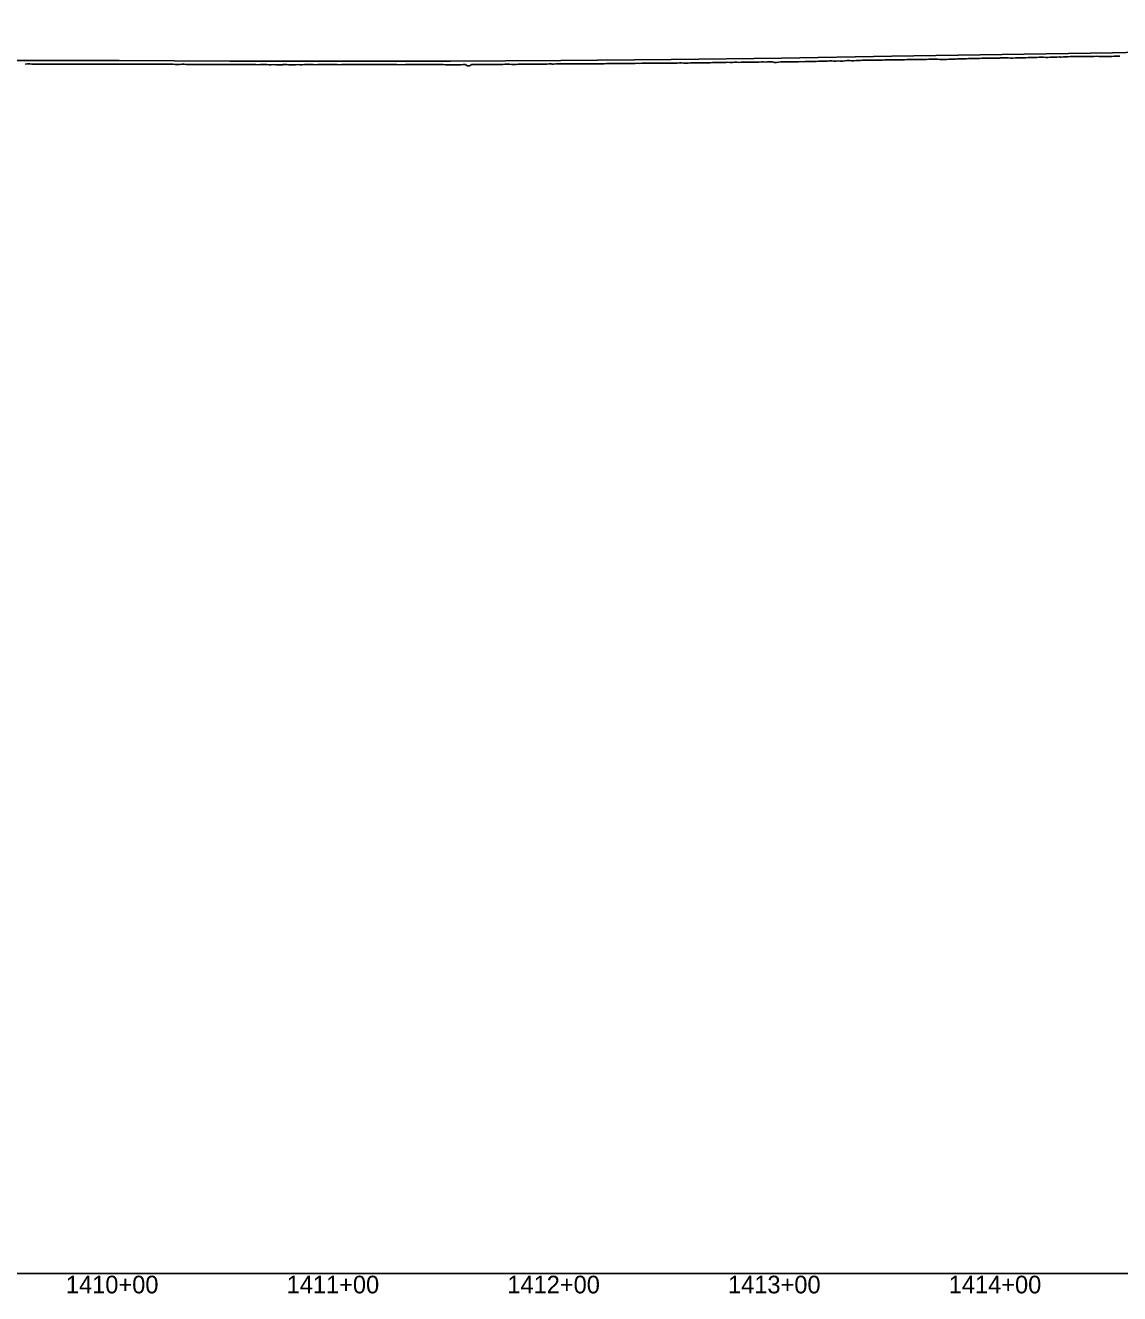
# Model space of a CAD drawing. Extents: x -3793 to 50787, y -1075 to 6138.
# Drawn here: x 28283 to 28779, y 2991 to 3566 of the extents above; entities that cross this region are included whole.
import ezdxf

# ---------------------------------------------------------------- set-up
doc = ezdxf.new("R2010")
doc.units = 0
for name, color, linetype in [('RD_DDB_Profile_EX', 7, 'Continuous'), ('RD_DDB_Profile_PR', 7, 'Continuous'), ('RD_DDB_StaTX', 7, 'Continuous'), ('RD_GPK_Profile_Cell', 7, 'Continuous')]:
    doc.layers.add(name, color=color, linetype=linetype)

msp = doc.modelspace()

# ---------------------------------------------------------------- linework, layer by layer
at = {"layer": 'RD_DDB_Profile_EX'}
for points in [[(28283.238508, 3548.117), (28284.232974, 3548.16193), (28285.312844, 3548.162625), (28286.238026, 3548.117085), (28287.231895, 3548.025065), (28288.236227, 3548.02389), (28289.316176, 3547.9783), (28290.232175, 3548.024735), (28291.31317, 3548.11187), (28291.877983, 3548.084065), (28292.238714, 3548.066225), (28293.310113, 3548.02396), (28294.235423, 3548.070475), (28295.316133, 3548.02279), (28296.232852, 3547.976725), (28297.312241, 3547.97316), (28298.237906, 3548.019695), (28298.885813, 3547.973355), (28299.889108, 3548.021675), (28300.882818, 3548.06394), (28301.885791, 3548.017785), (28302.88791, 3548.01794), (28303.890883, 3548.11034), (28304.883836, 3548.06784), (28305.416907, 3548.041355), (28305.886792, 3548.01776), (28306.889629, 3548.110085), (28307.882641, 3548.109595), (28308.885478, 3548.07094), (28309.888413, 3548.028325), (28310.890498, 3548.07445), (28311.884261, 3548.11638), (28312.186369, 3548.1013), (28312.887073, 3548.06994)], [(28312.887073, 3548.06994), (28313.889221, 3548.02324), (28314.870636, 3548.07271), (28315.87335, 3548.115065), (28316.876172, 3548.064775), (28317.869093, 3548.06418), (28318.95583, 3548.06402), (28319.874612, 3548.063545), (28320.877415, 3548.063025), (28321.870213, 3548.06234), (28322.873017, 3548.0155), (28323.87582, 3548.05764), (28324.869342, 3548.10334), (28325.872141, 3548.10645), (28326.874104, 3548.059455), (28327.876891, 3548.06231), (28328.870489, 3548.107665), (28329.873171, 3548.10348), (28330.875252, 3548.10272), (28331.86884, 3548.051705), (28332.494754, 3548.051245), (28332.871518, 3548.051015), (28333.874287, 3548.10005), (28334.868477, 3548.09359), (28335.87115, 3548.092775), (28336.873919, 3548.095205), (28338.235968, 3548.09582), (28339.264216, 3548.04977), (28340.229246, 3548.04705), (28341.230114, 3548.049405), (28342.231734, 3548.003475), (28343.232598, 3548.00418), (28344.234217, 3548.05125), (28345.235081, 3548.007165), (28346.236625, 3548.004255), (28347.237442, 3548.050985), (28348.238975, 3548.008525), (28349.230427, 3548.00689), (28350.231963, 3548.00723), (28351.232767, 3547.96488), (28352.234242, 3547.96538), (28352.803139, 3547.96679), (28353.234984, 3547.971185), (28354.236376, 3548.021455), (28355.237828, 3548.017845), (28356.238535, 3547.9254), (28357.239164, 3547.92758), (28358.240617, 3547.97014), (28359.24207, 3547.92782), (28359.572601, 3547.927805), (28360.226492, 3547.923935), (28361.226135, 3547.922125), (28362.227373, 3547.922305), (28363.228681, 3547.918505), (28364.229919, 3547.914845), (28365.230385, 3547.912735), (28366.342063, 3547.916785), (28367.232797, 3547.916755), (28368.234035, 3547.87043), (28369.234361, 3547.86824), (28370.235599, 3547.964135), (28371.227569, 3547.91773), (28372.227902, 3547.881235), (28373.229131, 3547.873125), (28374.230228, 3547.868915), (28375.231396, 3547.87241), (28376.23166, 3547.88181), (28377.232756, 3547.881515), (28378.233925, 3547.877125), (28378.843878, 3547.86459), (28379.880986, 3547.86586), (28380.766657, 3547.869235), (28381.846337, 3547.91098), (28382.767684, 3547.912065), (28383.76896, 3547.961445), (28384.769348, 3547.86487), (28385.848868, 3547.86824), (28386.770482, 3547.91542), (28387.771646, 3547.860785), (28388.85097, 3547.81783), (28389.763651, 3547.86459), (28390.764923, 3547.86763), (28391.766085, 3547.866895), (28392.767248, 3547.85457), (28393.767211, 3547.81307), (28394.76837, 3547.769855), (28395.846348, 3547.857275), (28396.769491, 3547.76568), (28397.770652, 3547.764715), (28398.771922, 3547.813605), (28399.848749, 3547.808915), (28400.189371, 3547.82629), (28400.763786, 3547.855465), (28401.76505, 3547.85419), (28402.766208, 3547.80678), (28403.766164, 3547.807195), (28404.767323, 3547.806025), (28405.768483, 3547.808545), (28406.958833, 3547.840485), (28407.768872, 3547.800235), (28408.770143, 3547.79874)], [(28408.770143, 3547.79874), (28409.843205, 3547.8474), (28410.761974, 3547.893865), (28411.763239, 3547.845965), (28412.782954, 3547.89456), (28413.783944, 3547.84318), (28414.783889, 3547.79665), (28415.784855, 3547.84157), (28416.634545, 3547.841215), (28417.634416, 3547.84132), (28418.634359, 3547.8413), (28419.63423, 3547.88796), (28420.634095, 3547.888035), (28421.633028, 3547.889455), (28422.632856, 3547.89283), (28423.632684, 3547.8962), (28424.632585, 3547.84596), (28425.632413, 3547.79237), (28426.632241, 3547.84226), (28427.632054, 3547.93514), (28428.631912, 3547.89162), (28429.631699, 3547.887845), (28430.631485, 3547.937525), (28431.631342, 3547.89394), (28432.639717, 3547.89383), (28433.639507, 3547.89008), (28434.03668, 3547.88995), (28434.639344, 3547.886095), (28435.639698, 3547.885705), (28436.639376, 3547.835295), (28437.639124, 3547.88476), (28438.638802, 3547.88435), (28439.638551, 3547.83382), (28440.806142, 3547.87159), (28441.637878, 3547.83282), (28442.636611, 3547.833735), (28443.636252, 3547.88311), (28444.635894, 3547.839105), (28445.636262, 3547.83834), (28446.635902, 3547.884405), (28447.63554, 3547.883745), (28448.635212, 3547.832765), (28449.634817, 3547.8319), (28450.634489, 3547.83092), (28451.634096, 3547.82688), (28452.632724, 3547.780895), (28453.632397, 3547.829915), (28454.631015, 3547.783885), (28455.630246, 3547.83134), (28456.638218, 3547.88208), (28457.636812, 3547.88271), (28458.635473, 3547.886465), (28459.634067, 3547.883845), (28460.632661, 3547.88119), (28461.114527, 3547.905615), (28461.631305, 3547.931575), (28462.629865, 3547.93857), (28463.637715, 3547.932595), (28464.636342, 3547.882875), (28465.636535, 3547.88492), (28466.635095, 3547.88533), (28467.883989, 3547.923185), (28468.632259, 3547.88586), (28469.630855, 3547.885935), (28470.63867, 3547.889675), (28471.637196, 3547.84653), (28472.635792, 3547.846605), (28473.634318, 3547.80015), (28474.653451, 3547.79704), (28475.632074, 3547.79688), (28476.63057, 3547.796855), (28477.639396, 3547.79841), (28478.637891, 3547.748385), (28479.636318, 3547.74849), (28480.634813, 3547.79516), (28481.63389, 3547.84193), (28482.632355, 3547.88838), (28483.630751, 3547.32776), (28484.629148, 3547.327595), (28485.636908, 3547.83811), (28486.635959, 3547.888), (28487.634424, 3547.89103), (28488.192374, 3547.89089), (28488.632808, 3547.887525), (28489.630202, 3547.88893), (28490.637613, 3547.8871), (28491.635981, 3547.936765), (28492.633444, 3547.898105), (28493.631811, 3547.894385), (28494.629879, 3547.942445), (28494.961836, 3547.94237), (28495.637571, 3547.938665), (28496.634938, 3547.89323), (28497.633348, 3547.89593), (28498.630714, 3547.943715), (28499.639001, 3547.893385), (28500.636438, 3547.991), (28501.731298, 3548.03229), (28502.632192, 3547.98783), (28503.630223, 3547.945695), (28504.637792, 3547.90549)], [(28504.637792, 3547.90549), (28505.635205, 3547.89595), (28506.633517, 3547.995165), (28507.631622, 3548.04601), (28508.639186, 3548.04195), (28509.636502, 3547.992665), (28510.634863, 3548.04155), (28511.632179, 3548.0888), (28512.631153, 3548.04474), (28513.637803, 3547.99903), (28514.635119, 3548.003265), (28515.633471, 3547.99853), (28516.631454, 3548.045605), (28517.638977, 3548.09459), (28518.636342, 3548.04842), (28519.634608, 3548.09031), (28520.632585, 3548.18396), (28521.630916, 3548.139495), (28522.039683, 3548.1195), (28522.637467, 3548.090075), (28523.635713, 3548.18527), (28524.633659, 3548.13895), (28525.630932, 3548.142625), (28526.637546, 3548.1896), (28527.634818, 3548.18988), (28528.809145, 3548.228395), (28529.638319, 3548.195665), (28530.635643, 3548.1956), (28531.632895, 3548.2422), (28532.630838, 3548.24228), (28533.637346, 3548.24255), (28534.634671, 3548.245965), (28535.630953, 3548.204795), (28536.638133, 3548.25135), (28537.635366, 3548.25119), (28538.632672, 3548.247385), (28539.639154, 3548.20095), (28540.637085, 3548.204315), (28541.633351, 3548.209515), (28542.630579, 3548.25928), (28543.637112, 3548.255425), (28544.63503, 3548.248), (28545.632245, 3548.20465), (28546.638709, 3548.30096), (28547.635999, 3548.35044), (28548.632243, 3548.308895), (28549.11753, 3548.308695), (28549.630151, 3548.304865), (28550.636598, 3548.304455), (28551.633872, 3548.30369), (28552.631072, 3548.306545), (28553.638219, 3548.30961), (28554.634448, 3548.357355), (28555.886992, 3548.36915), (28556.638166, 3548.39905), (28557.636041, 3548.39823), (28558.633226, 3548.307675), (28559.629369, 3548.355365), (28560.636428, 3548.444535), (28561.633543, 3548.400695), (28562.656453, 3548.496915), (28563.636803, 3548.447505), (28564.633905, 3548.44657), (28565.631682, 3548.49565), (28566.637082, 3548.4967), (28567.634256, 3548.44902), (28568.632029, 3548.49808), (28569.638407, 3548.49728), (28570.634523, 3548.497915), (28571.63235, 3548.449935), (28572.629439, 3548.45202), (28573.635504, 3548.54627), (28574.632594, 3548.54507), (28575.629753, 3548.497015), (28576.195377, 3548.49638), (28576.636786, 3548.49591), (28577.632893, 3548.53982), (28578.629976, 3548.494855), (28579.637072, 3548.590295), (28580.634156, 3548.585705), (28581.630263, 3548.539265), (28582.637294, 3548.541185), (28582.964839, 3548.540655), (28583.634375, 3548.54265), (28584.631155, 3548.58651), (28585.637562, 3548.63197), (28586.634643, 3548.583355), (28587.63232, 3548.58468), (28588.628481, 3548.634735), (28589.7343, 3548.638025), (28590.632571, 3548.67254), (28591.629642, 3548.670705), (28592.635738, 3548.67362), (28593.632809, 3548.674565), (28594.629883, 3548.814275), (28595.635919, 3548.81442), (28596.631026, 3548.816075), (28597.636493, 3548.771645), (28598.632159, 3548.77319), (28599.628183, 3548.81729), (28600.633232, 3548.871855)], [(28600.633232, 3548.871855), (28601.629256, 3548.915885), (28602.634306, 3548.870445), (28603.689306, 3548.87018), (28604.635373, 3548.918675), (28605.690292, 3548.921225), (28606.635841, 3548.875675), (28607.691868, 3548.92228), (28608.627554, 3549.01752), (28609.633579, 3548.970245), (28610.042686, 3548.97005), (28610.689811, 3548.97271), (28611.634636, 3548.92698), (28612.690565, 3548.92933), (28613.635087, 3548.9776), (28614.631767, 3548.9299), (28615.636204, 3548.928115), (28616.812147, 3549.039775), (28617.627919, 3549.07837), (28618.633874, 3549.02469), (28619.62897, 3549.07549), (28620.634925, 3549.077915), (28621.630021, 3549.122605), (28622.696707, 3548.752425), (28623.631072, 3548.84732), (28624.697725, 3548.93711), (28625.632121, 3549.125575), (28626.628192, 3549.07746), (28627.633234, 3549.12215), (28628.629241, 3549.17114), (28629.633676, 3549.081025), (28630.63029, 3549.079885), (28631.634728, 3549.171355), (28632.691135, 3549.129065), (28633.63578, 3549.176705), (28634.691709, 3549.22712), (28635.697011, 3549.177805), (28636.692275, 3549.22829), (28637.120533, 3549.22858), (28637.697517, 3549.228845), (28638.631501, 3549.229095), (28639.697882, 3549.28253), (28640.693042, 3549.28589), (28641.697473, 3549.285065), (28642.693263, 3549.3322), (28643.889994, 3549.382695), (28644.630012, 3549.382725), (28645.698005, 3549.336005), (28646.693696, 3549.38606), (28647.698154, 3549.483115), (28648.693847, 3549.48317), (28649.698303, 3549.342915), (28650.693993, 3549.34932), (28651.635124, 3549.489795), (28652.693949, 3549.445825), (28653.698304, 3549.44899), (28654.693896, 3549.586135), (28655.698251, 3549.63613), (28656.693842, 3549.642285), (28657.635279, 3549.548565), (28658.693671, 3549.50426), (28659.69793, 3549.64771), (28660.693417, 3549.74101), (28661.697679, 3549.740765), (28662.693163, 3549.790345), (28663.697428, 3549.833875), (28664.19838, 3549.834635), (28664.629544, 3549.83519), (28665.696896, 3549.79397), (28666.691656, 3549.890175), (28667.696449, 3549.839705), (28668.691209, 3549.889035), (28669.696002, 3549.935485), (28670.629776, 3549.88794), (28670.967841, 3549.9046), (28671.695493, 3549.934085), (28672.690148, 3549.983325), (28673.694834, 3550.026715), (28674.689956, 3550.030795), (28675.694032, 3549.98325), (28676.689291, 3550.07346), (28677.737303, 3550.075875), (28678.688535, 3550.07795), (28679.693123, 3550.08011), (28680.687679, 3549.984975), (28681.692267, 3550.07537), (28682.686823, 3550.171495), (28683.691411, 3550.173585), (28684.686394, 3550.17439), (28685.690307, 3550.17334), (28686.685339, 3550.127815), (28687.689263, 3550.1739), (28688.684285, 3550.21987), (28689.688774, 3550.21883), (28690.683231, 3550.170335), (28691.276227, 3550.19916), (28691.687681, 3550.21917), (28692.682045, 3550.265), (28693.68644, 3550.26107), (28694.681207, 3550.256145), (28695.685069, 3550.30494)], [(28695.685069, 3550.30494), (28696.679953, 3550.306175), (28697.683829, 3550.212615), (28698.045688, 3550.194085), (28698.688165, 3550.16114), (28699.682936, 3550.206915), (28700.68674, 3550.20537), (28701.681497, 3550.298845), (28702.685316, 3550.34737), (28703.680058, 3550.30041), (28704.81515, 3550.31397), (28705.678295, 3550.39835), (28706.682498, 3550.396615), (28707.676544, 3550.39663), (28708.680624, 3550.44442), (28709.674676, 3550.494345), (28710.678756, 3550.54444), (28711.682951, 3550.54272), (28712.676912, 3550.59017), (28713.680907, 3550.63996), (28714.674868, 3550.63967), (28715.678863, 3550.63946), (28716.672824, 3550.73694), (28717.676942, 3550.739395), (28718.680902, 3550.737015), (28719.67478, 3550.736435), (28720.678679, 3550.783935), (28721.672557, 3550.785505), (28722.676579, 3550.739665), (28723.680068, 3550.782985), (28724.674356, 3550.830425), (28725.123535, 3550.852645), (28725.677801, 3550.88399), (28726.671996, 3550.8792), (28727.675539, 3550.876865), (28728.669719, 3550.878125), (28729.673535, 3550.82943), (28730.67696, 3550.83077), (28731.892997, 3550.938555), (28732.674631, 3550.975495), (28733.668699, 3550.974545), (28734.672066, 3550.92547), (28735.666125, 3550.972725), (28736.669501, 3550.971855), (28737.673229, 3551.022795), (28738.667401, 3551.021575), (28739.670578, 3551.019025), (28740.664533, 3551.017795), (28741.667712, 3551.116905), (28742.671359, 3551.165855), (28743.664845, 3551.168125), (28744.668492, 3551.217055), (28745.671651, 3551.121085), (28746.665522, 3551.119575), (28747.668623, 3551.168525), (28748.672192, 3551.215605), (28749.665917, 3551.21602), (28750.669163, 3551.26315), (28751.662883, 3551.313555), (28752.201382, 3551.28608), (28752.666092, 3551.26381), (28753.66958, 3551.35927), (28754.662897, 3551.409505), (28755.666376, 3551.40968), (28756.669715, 3551.457065), (28757.663173, 3551.505635), (28758.666512, 3551.50748), (28758.970844, 3551.4919), (28759.669936, 3551.45745), (28760.663462, 3551.45892), (28761.666574, 3551.455905), (28762.660093, 3551.45454), (28763.663485, 3551.45572), (28764.666472, 3551.458625), (28765.740306, 3551.460625), (28766.663437, 3551.50358), (28767.666363, 3551.55226), (28768.659778, 3551.60081), (28769.66296, 3551.45458), (28770.665745, 3551.503805), (28771.659169, 3551.55362), (28772.662206, 3551.50805), (28773.66504, 3551.506435), (28774.668004, 3551.50801), (28775.661364, 3551.5576), (28776.664194, 3551.607335), (28777.667158, 3551.656105), (28778.660522, 3551.60711), (28779.279229, 3551.638935)]]:
    msp.add_lwpolyline(points, dxfattribs=at)
at = {"layer": 'RD_DDB_Profile_PR'}
msp.add_lwpolyline([(28275.9, 3549.716), (28325.9, 3549.7055), (28375.9, 3549.4785), (28425.9, 3549.4055), (28475.9, 3549.397), (28525.9, 3549.755), (28575.9, 3550.0965), (28625.9, 3550.713), (28675.9, 3551.601), (28725.9, 3552.483), (28775.9, 3553.169), (28825.9, 3554.3855), (28875.9, 3555.8025), (28925.9, 3557.5585), (28975.9, 3558.875), (29025.9, 3559.9635), (29075.9, 3560.998), (29125.9, 3561.9285), (29175.9, 3563.101), (29225.9, 3564.437), (29275.9, 3565.6315)], dxfattribs=at)
at = {"layer": 'RD_GPK_Profile_Cell'}
msp.add_line((1000, 3000), (46549.603806, 3000), dxfattribs=at)

# ---------------------------------------------------------------- texts
at = {"layer": 'RD_DDB_StaTX'}
for s, p in [('1410+00', (28301.687695, 2991)), ('1410+00', (28301.695471, 2991)), ('1411+00', (28401.687695, 2991)), ('1411+00', (28401.695471, 2991)), ('1412+00', (28501.687695, 2991)), ('1412+00', (28501.695471, 2991)), ('1413+00', (28601.687695, 2991)), ('1413+00', (28601.695471, 2991)), ('1414+00', (28701.687695, 2991)), ('1414+00', (28701.695471, 2991))]:
    msp.add_text(s, height=8, dxfattribs=at).set_placement(p)

doc.saveas('drawing.dxf')
